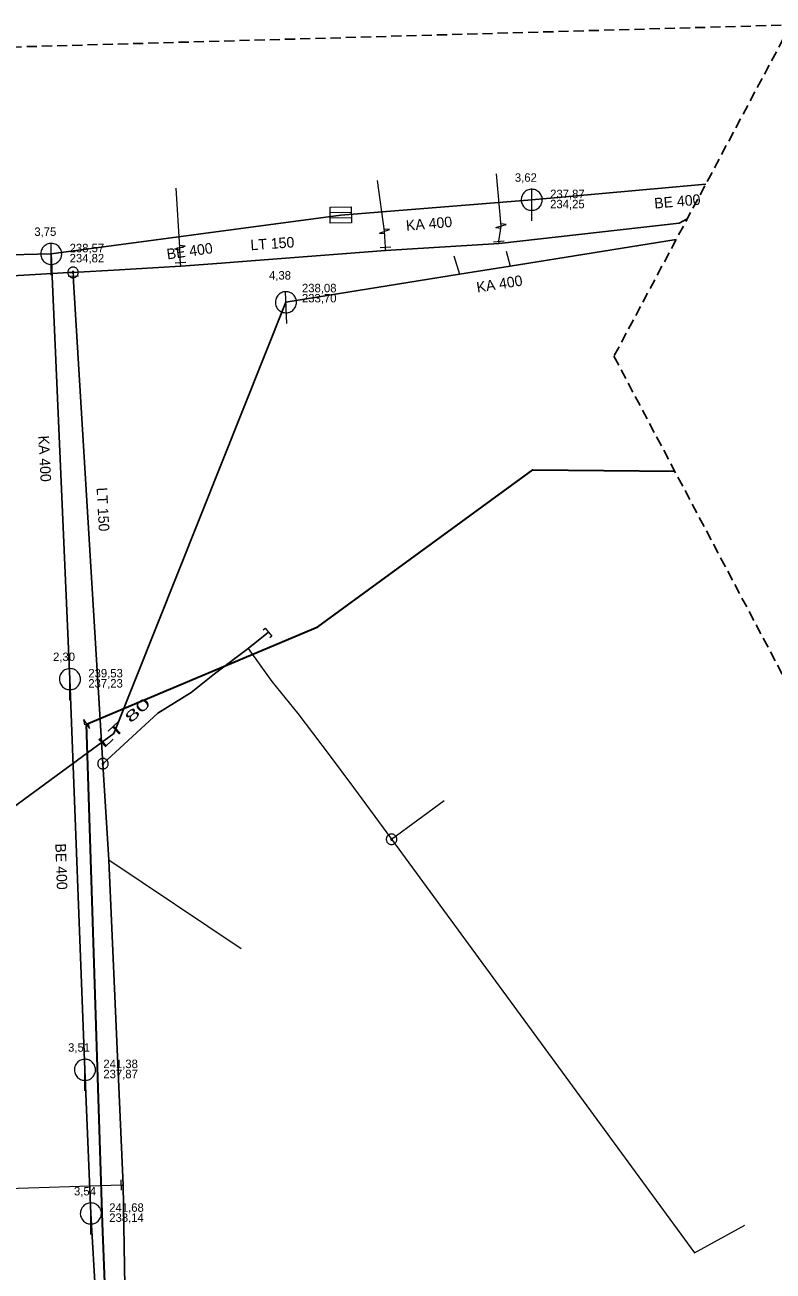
# Model space of a CAD drawing. Extents: x -777996 to -777727, y -976581 to -976199.
# Drawn here: x -777920.7 to -777849.8, y -976316.9 to -976198.8 of the extents above; entities that cross this region are included whole.
import ezdxf

# ---------------------------------------------------------------- set-up
doc = ezdxf.new("R2010")
doc.units = 0
doc.header["$LTSCALE"] = 0.32
doc.linetypes.add('MEDIUM_DASHED', pattern=[4.5, 3, -1.5])
for name, color, linetype, lineweight in [('1', 7, 'MEDIUM_DASHED', 25), ('11', 7, 'Continuous', 13), ('13', 7, 'Continuous', 13), ('14', 7, 'Continuous', 25), ('17', 7, 'Continuous', 25), ('22', 7, 'Continuous', 13), ('34', 7, 'Continuous', 13), ('47', 7, 'Continuous', 13)]:
    doc.layers.add(name, color=color, linetype=linetype, lineweight=lineweight)

msp = doc.modelspace()

# ---------------------------------------------------------------- linework, layer by layer
at = {"layer": '1'}
msp.add_lwpolyline([(-777995.417, -976203.033), (-777848.18, -976198.846), (-777864.927, -976230.247), (-777726.762, -976491.225), (-777789.565, -976581.242), (-777941.686, -976558.215), (-777989.136, -976405.396)], close=True, dxfattribs=at)
at = {"layer": '11'}
for p, q in [((-777880.085, -976220.714), (-777879.559, -976222.48)), ((-777875.137, -976220.301), (-777874.77, -976221.71))]:
    msp.add_line(p, q, dxfattribs=at)
at = {"layer": '13'}
for p, q in [((-777886.67, -976218.399), (-777887.346, -976213.598)), ((-777875.62, -976217.91), (-777876.065, -976212.971)), ((-777906.059, -976219.949), (-777906.417, -976214.321)), ((-777886.579, -976219.92), (-777886.67, -976218.399)), ((-777875.84, -976219.35), (-777875.62, -976217.91)), ((-777886.003, -976276.015), (-777881.024, -976272.355)), ((-777900.252, -976286.394), (-777912.789, -976277.989)), ((-777911.609, -976308.78), (-777933.447, -976309.493))]:
    msp.add_line(p, q, dxfattribs=at)
for points in [[(-777905.996, -976221.36), (-777906.014, -976221.018), (-777906.064, -976219.872)], [(-777899.57, -976257.94), (-777897.34, -976261.07), (-777894.89, -976264.09), (-777891.899, -976268), (-777889.601, -976271.12), (-777886.003, -976276.015)], [(-777886.003, -976276.015), (-777857.296, -976315.2), (-777852.537, -976312.587)]]:
    msp.add_lwpolyline(points, dxfattribs=at)
at = {"layer": '14'}
for p, q in [((-777872.715, -976215.421), (-777856.22, -976213.921)), ((-777890.804, -976216.868), (-777872.715, -976215.421)), ((-777918.245, -976220.55), (-777890.804, -976216.868)), ((-777935.509, -976220.899), (-777918.245, -976220.55)), ((-777916.475, -976260.84), (-777918.245, -976220.55)), ((-777915.05, -976297.862), (-777916.475, -976260.84)), ((-777914.489, -976311.478), (-777915.05, -976297.862)), ((-777912.781, -976340.699), (-777914.489, -976311.478))]:
    msp.add_line(p, q, dxfattribs=at)
at = {"layer": '14', "lineweight": 13}
for p, q in [((-777875.805, -976219.573), (-777875.84, -976219.35)), ((-777886.559, -976220.219), (-777886.579, -976219.92)), ((-777905.98, -976221.699), (-777905.996, -976221.36)), ((-777916.18, -976222.3), (-777916.155, -976222.666)), ((-777911.609, -976308.78), (-777911.427, -976308.781))]:
    msp.add_line(p, q, dxfattribs=at)
at = {"layer": '14'}
for points in [[(-777896.01, -976225.129), (-777879.559, -976222.48), (-777874.77, -976221.71), (-777859.024, -976219.178)], [(-777960.831, -976301.607), (-777912.32, -976266.008), (-777896.01, -976225.129)]]:
    msp.add_lwpolyline(points, dxfattribs=at)
at = {"layer": '17'}
msp.add_line((-777916.155, -976222.666), (-777913.344, -976268.857), dxfattribs=at)
for points in [[(-777916.18, -976222.3), (-777915.685, -976222.266), (-777912.3, -976222.1), (-777905.98, -976221.699), (-777902.108, -976221.408), (-777900.93, -976221.32), (-777886.559, -976220.219), (-777875.805, -976219.573), (-777858.75, -976217.62), (-777857.98, -976217.22)], [(-777929.246, -976223.038), (-777928.877, -976223.029), (-777916.57, -976222.32), (-777916.18, -976222.3)], [(-777913.344, -976268.857), (-777908.149, -976264.079), (-777904.989, -976262.12), (-777902.789, -976260.329), (-777899.57, -976257.94), (-777897.657, -976256.389)], [(-777913.344, -976268.857), (-777912.789, -976277.989), (-777911.427, -976308.781), (-777911.171, -976324.191), (-777910.419, -976354.125), (-777909.559, -976388.363), (-777908.825, -976391.646), (-777908.211, -976394.397)]]:
    msp.add_lwpolyline(points, dxfattribs=at)
at = {"layer": '17', "lineweight": 35}
for points in [[(-777914.899, -976265.1), (-777893, -976255.899), (-777872.6, -976241), (-777859.156, -976241.149)], [(-777904.212, -976563.887), (-777912, -976559.699), (-777928.6, -976551.899), (-777943.399, -976543.899), (-777945.899, -976539.199), (-777934, -976487.1), (-777919.8, -976463.1), (-777903.899, -976437), (-777908, -976421.399), (-777910, -976398.3), (-777913.399, -976312.399), (-777914.899, -976265.1)]]:
    msp.add_lwpolyline(points, dxfattribs=at)
at = {"layer": '22'}
for p, q in [((-777872.716, -976217.421), (-777872.715, -976214.421)), ((-777891.818, -976216.626), (-777889.818, -976216.597)), ((-777891.811, -976217.126), (-777889.811, -976217.096)), ((-777918.246, -976222.55), (-777918.245, -976219.55)), ((-777895.931, -976227.127), (-777896.049, -976224.13)), ((-777916.475, -976262.84), (-777916.474, -976259.84)), ((-777915.051, -976299.862), (-777915.05, -976296.862)), ((-777914.49, -976313.478), (-777914.489, -976310.478))]:
    msp.add_line(p, q, dxfattribs=at)
for points in [[(-777871.716, -976215.421), (-777871.721, -976215.312), (-777871.739, -976215.204), (-777871.769, -976215.098), (-777871.809, -976214.997), (-777871.861, -976214.9), (-777871.923, -976214.81), (-777871.995, -976214.727), (-777872.075, -976214.653), (-777872.163, -976214.587), (-777872.257, -976214.532), (-777872.357, -976214.487), (-777872.462, -976214.454), (-777872.569, -976214.432), (-777872.678, -976214.422), (-777872.788, -976214.424), (-777872.896, -976214.438), (-777873.003, -976214.463), (-777873.106, -976214.5), (-777873.204, -976214.549), (-777873.296, -976214.607), (-777873.382, -976214.676), (-777873.459, -976214.753), (-777873.528, -976214.839), (-777873.587, -976214.931), (-777873.635, -976215.029), (-777873.672, -976215.132), (-777873.698, -976215.239), (-777873.712, -976215.347), (-777873.715, -976215.457), (-777873.705, -976215.566), (-777873.684, -976215.673), (-777873.65, -976215.777), (-777873.606, -976215.877), (-777873.551, -976215.972), (-777873.485, -976216.06), (-777873.411, -976216.14), (-777873.328, -976216.212), (-777873.238, -976216.274), (-777873.142, -976216.326), (-777873.04, -976216.367), (-777872.935, -976216.397), (-777872.827, -976216.415), (-777872.717, -976216.421), (-777872.608, -976216.415), (-777872.5, -976216.397), (-777872.395, -976216.368), (-777872.293, -976216.327), (-777872.196, -976216.275), (-777872.106, -976216.213), (-777872.023, -976216.142), (-777871.948, -976216.062), (-777871.883, -976215.974), (-777871.827, -976215.88), (-777871.783, -976215.78), (-777871.749, -976215.676), (-777871.727, -976215.568), (-777871.717, -976215.459)], [(-777891.825, -976216.126), (-777889.826, -976216.097), (-777889.804, -976217.596), (-777891.803, -976217.626)], [(-777917.246, -976220.55), (-777917.251, -976220.441), (-777917.269, -976220.333), (-777917.299, -976220.227), (-777917.339, -976220.126), (-777917.391, -976220.029), (-777917.453, -976219.939), (-777917.525, -976219.856), (-777917.605, -976219.782), (-777917.693, -976219.716), (-777917.787, -976219.661), (-777917.887, -976219.616), (-777917.992, -976219.583), (-777918.099, -976219.561), (-777918.208, -976219.551), (-777918.318, -976219.553), (-777918.426, -976219.567), (-777918.533, -976219.592), (-777918.636, -976219.629), (-777918.734, -976219.678), (-777918.826, -976219.736), (-777918.912, -976219.805), (-777918.989, -976219.882), (-777919.058, -976219.968), (-777919.117, -976220.06), (-777919.165, -976220.158), (-777919.202, -976220.261), (-777919.228, -976220.368), (-777919.242, -976220.476), (-777919.245, -976220.586), (-777919.235, -976220.695), (-777919.214, -976220.802), (-777919.18, -976220.906), (-777919.136, -976221.006), (-777919.081, -976221.101), (-777919.015, -976221.189), (-777918.941, -976221.269), (-777918.858, -976221.341), (-777918.768, -976221.403), (-777918.672, -976221.455), (-777918.57, -976221.496), (-777918.465, -976221.526), (-777918.357, -976221.544), (-777918.247, -976221.55), (-777918.138, -976221.544), (-777918.03, -976221.526), (-777917.925, -976221.497), (-777917.823, -976221.456), (-777917.726, -976221.404), (-777917.636, -976221.342), (-777917.553, -976221.271), (-777917.478, -976221.191), (-777917.413, -976221.103), (-777917.357, -976221.009), (-777917.313, -976220.909), (-777917.279, -976220.805), (-777917.257, -976220.697), (-777917.247, -976220.588)], [(-777895.01, -976225.09), (-777895.021, -976224.981), (-777895.043, -976224.874), (-777895.077, -976224.769), (-777895.121, -976224.67), (-777895.177, -976224.575), (-777895.242, -976224.487), (-777895.317, -976224.407), (-777895.4, -976224.336), (-777895.491, -976224.274), (-777895.587, -976224.223), (-777895.689, -976224.182), (-777895.795, -976224.153), (-777895.903, -976224.135), (-777896.012, -976224.129), (-777896.122, -976224.136), (-777896.229, -976224.154), (-777896.335, -976224.183), (-777896.436, -976224.224), (-777896.532, -976224.277), (-777896.622, -976224.339), (-777896.705, -976224.411), (-777896.779, -976224.491), (-777896.845, -976224.58), (-777896.9, -976224.674), (-777896.944, -976224.774), (-777896.977, -976224.878), (-777896.999, -976224.986), (-777897.009, -976225.094), (-777897.006, -976225.204), (-777896.992, -976225.313), (-777896.967, -976225.419), (-777896.929, -976225.522), (-777896.881, -976225.62), (-777896.822, -976225.712), (-777896.753, -976225.798), (-777896.676, -976225.875), (-777896.59, -976225.944), (-777896.497, -976226.002), (-777896.399, -976226.05), (-777896.296, -976226.087), (-777896.19, -976226.113), (-777896.081, -976226.127), (-777895.971, -976226.128), (-777895.862, -976226.118), (-777895.755, -976226.096), (-777895.651, -976226.063), (-777895.551, -976226.018), (-777895.456, -976225.962), (-777895.369, -976225.896), (-777895.289, -976225.822), (-777895.217, -976225.739), (-777895.155, -976225.649), (-777895.103, -976225.553), (-777895.063, -976225.451), (-777895.033, -976225.346), (-777895.015, -976225.237), (-777895.01, -976225.128)], [(-777915.475, -976260.84), (-777915.48, -976260.731), (-777915.498, -976260.623), (-777915.528, -976260.517), (-777915.568, -976260.416), (-777915.62, -976260.319), (-777915.682, -976260.229), (-777915.754, -976260.146), (-777915.834, -976260.072), (-777915.922, -976260.006), (-777916.016, -976259.951), (-777916.116, -976259.906), (-777916.221, -976259.873), (-777916.328, -976259.851), (-777916.437, -976259.841), (-777916.547, -976259.843), (-777916.655, -976259.857), (-777916.762, -976259.882), (-777916.865, -976259.919), (-777916.963, -976259.968), (-777917.055, -976260.026), (-777917.141, -976260.095), (-777917.218, -976260.172), (-777917.287, -976260.258), (-777917.346, -976260.35), (-777917.394, -976260.448), (-777917.431, -976260.551), (-777917.457, -976260.658), (-777917.471, -976260.766), (-777917.474, -976260.876), (-777917.464, -976260.985), (-777917.443, -976261.092), (-777917.409, -976261.196), (-777917.365, -976261.296), (-777917.31, -976261.391), (-777917.244, -976261.479), (-777917.17, -976261.559), (-777917.087, -976261.631), (-777916.997, -976261.693), (-777916.901, -976261.745), (-777916.799, -976261.786), (-777916.694, -976261.816), (-777916.586, -976261.834), (-777916.476, -976261.84), (-777916.367, -976261.834), (-777916.259, -976261.816), (-777916.154, -976261.787), (-777916.052, -976261.746), (-777915.955, -976261.694), (-777915.865, -976261.632), (-777915.782, -976261.561), (-777915.707, -976261.481), (-777915.642, -976261.393), (-777915.586, -976261.299), (-777915.542, -976261.199), (-777915.508, -976261.095), (-777915.486, -976260.987), (-777915.476, -976260.878)], [(-777914.051, -976297.862), (-777914.056, -976297.753), (-777914.074, -976297.645), (-777914.104, -976297.539), (-777914.144, -976297.438), (-777914.196, -976297.341), (-777914.258, -976297.251), (-777914.33, -976297.168), (-777914.41, -976297.094), (-777914.498, -976297.028), (-777914.592, -976296.973), (-777914.692, -976296.928), (-777914.797, -976296.895), (-777914.904, -976296.873), (-777915.013, -976296.863), (-777915.123, -976296.865), (-777915.231, -976296.879), (-777915.338, -976296.904), (-777915.441, -976296.941), (-777915.539, -976296.99), (-777915.631, -976297.048), (-777915.717, -976297.117), (-777915.794, -976297.194), (-777915.863, -976297.28), (-777915.922, -976297.372), (-777915.97, -976297.47), (-777916.007, -976297.573), (-777916.033, -976297.68), (-777916.047, -976297.788), (-777916.05, -976297.898), (-777916.04, -976298.007), (-777916.019, -976298.114), (-777915.985, -976298.218), (-777915.941, -976298.318), (-777915.886, -976298.413), (-777915.82, -976298.501), (-777915.746, -976298.581), (-777915.663, -976298.653), (-777915.573, -976298.715), (-777915.477, -976298.767), (-777915.375, -976298.808), (-777915.27, -976298.838), (-777915.162, -976298.856), (-777915.052, -976298.862), (-777914.943, -976298.856), (-777914.835, -976298.838), (-777914.73, -976298.809), (-777914.628, -976298.768), (-777914.531, -976298.716), (-777914.441, -976298.654), (-777914.358, -976298.583), (-777914.283, -976298.503), (-777914.218, -976298.415), (-777914.162, -976298.321), (-777914.118, -976298.221), (-777914.084, -976298.117), (-777914.062, -976298.009), (-777914.052, -976297.9)], [(-777913.49, -976311.478), (-777913.495, -976311.369), (-777913.513, -976311.261), (-777913.543, -976311.155), (-777913.583, -976311.054), (-777913.635, -976310.957), (-777913.697, -976310.867), (-777913.769, -976310.784), (-777913.849, -976310.71), (-777913.937, -976310.644), (-777914.031, -976310.589), (-777914.131, -976310.544), (-777914.236, -976310.511), (-777914.343, -976310.489), (-777914.452, -976310.479), (-777914.562, -976310.481), (-777914.67, -976310.495), (-777914.777, -976310.52), (-777914.88, -976310.557), (-777914.978, -976310.606), (-777915.07, -976310.664), (-777915.156, -976310.733), (-777915.233, -976310.81), (-777915.302, -976310.896), (-777915.361, -976310.988), (-777915.409, -976311.086), (-777915.446, -976311.189), (-777915.472, -976311.296), (-777915.486, -976311.404), (-777915.489, -976311.514), (-777915.479, -976311.623), (-777915.458, -976311.73), (-777915.424, -976311.834), (-777915.38, -976311.934), (-777915.325, -976312.029), (-777915.259, -976312.117), (-777915.185, -976312.197), (-777915.102, -976312.269), (-777915.012, -976312.331), (-777914.916, -976312.383), (-777914.814, -976312.424), (-777914.709, -976312.454), (-777914.601, -976312.472), (-777914.491, -976312.478), (-777914.382, -976312.472), (-777914.274, -976312.454), (-777914.169, -976312.425), (-777914.067, -976312.384), (-777913.97, -976312.332), (-777913.88, -976312.27), (-777913.797, -976312.199), (-777913.722, -976312.119), (-777913.657, -976312.031), (-777913.601, -976311.937), (-777913.557, -976311.837), (-777913.523, -976311.733), (-777913.501, -976311.625), (-777913.491, -976311.516)]]:
    msp.add_lwpolyline(points, close=True, dxfattribs=at)
at = {"layer": '34'}
for p, q in [((-777876.337, -976219.397), (-777875.342, -976219.303)), ((-777887.077, -976219.953), (-777886.08, -976219.887)), ((-777906.495, -976221.384), (-777905.496, -976221.336)), ((-777915.655, -976222.645), (-777916.654, -976222.685)), ((-777911.592, -976309.279), (-777911.624, -976308.28))]:
    msp.add_line(p, q, dxfattribs=at)
at = {"layer": '47'}
for p, q in [((-777887.151, -976218.565), (-777886.641, -976218.598)), ((-777876.109, -976218.052), (-777875.601, -976218.11)), ((-777906.551, -976220.078), (-777906.046, -976220.149)), ((-777915.184, -976264.676), (-777915.085, -976265.177))]:
    msp.add_line(p, q, dxfattribs=at)
for points in [[(-777887.151, -976218.565), (-777886.188, -976218.232), (-777886.698, -976218.199)], [(-777876.109, -976218.052), (-777875.13, -976217.767), (-777875.638, -976217.709)], [(-777906.551, -976220.078), (-777905.566, -976219.819), (-777906.071, -976219.748)], [(-777898.173, -976256.181), (-777897.983, -976256.015), (-777897.33, -976256.762), (-777897.52, -976256.928)], [(-777915.184, -976264.676), (-777914.615, -976265.523), (-777914.714, -976265.022)]]:
    msp.add_lwpolyline(points, dxfattribs=at)
for points in [[(-777915.68, -976222.273), (-777915.686, -976222.221), (-777915.697, -976222.169), (-777915.713, -976222.12), (-777915.734, -976222.072), (-777915.761, -976222.027), (-777915.792, -976221.984), (-777915.827, -976221.946), (-777915.866, -976221.911), (-777915.908, -976221.88), (-777915.953, -976221.854), (-777916.001, -976221.832), (-777916.051, -976221.817), (-777916.102, -976221.806), (-777916.154, -976221.8), (-777916.206, -976221.8), (-777916.258, -976221.806), (-777916.31, -976221.817), (-777916.36, -976221.834), (-777916.407, -976221.854), (-777916.452, -976221.881), (-777916.495, -976221.912), (-777916.534, -976221.947), (-777916.569, -976221.986), (-777916.6, -976222.028), (-777916.625, -976222.073), (-777916.647, -976222.121), (-777916.663, -976222.171), (-777916.673, -976222.222), (-777916.679, -976222.274), (-777916.679, -976222.326), (-777916.673, -976222.378), (-777916.662, -976222.43), (-777916.646, -976222.48), (-777916.625, -976222.527), (-777916.598, -976222.572), (-777916.568, -976222.615), (-777916.533, -976222.654), (-777916.494, -976222.689), (-777916.451, -976222.72), (-777916.406, -976222.745), (-777916.358, -976222.767), (-777916.309, -976222.783), (-777916.257, -976222.793), (-777916.205, -976222.799), (-777916.153, -976222.799), (-777916.101, -976222.793), (-777916.049, -976222.782), (-777916, -976222.767), (-777915.952, -976222.745), (-777915.907, -976222.718), (-777915.864, -976222.688), (-777915.826, -976222.653), (-777915.791, -976222.614), (-777915.76, -976222.571), (-777915.734, -976222.526), (-777915.712, -976222.478), (-777915.697, -976222.429), (-777915.686, -976222.377), (-777915.68, -976222.325)], [(-777916.098, -976222.295), (-777916.098, -976222.286), (-777916.101, -976222.278), (-777916.103, -976222.27), (-777916.106, -976222.263), (-777916.111, -976222.255), (-777916.116, -976222.248), (-777916.122, -976222.241), (-777916.128, -976222.236), (-777916.135, -976222.231), (-777916.142, -976222.226), (-777916.151, -976222.223), (-777916.159, -976222.22), (-777916.167, -976222.219), (-777916.175, -976222.217), (-777916.184, -976222.218), (-777916.193, -976222.218), (-777916.201, -976222.221), (-777916.209, -976222.223), (-777916.216, -976222.226), (-777916.224, -976222.231), (-777916.231, -976222.236), (-777916.238, -976222.242), (-777916.243, -976222.248), (-777916.249, -976222.255), (-777916.253, -976222.262), (-777916.256, -976222.271), (-777916.259, -976222.279), (-777916.26, -976222.287), (-777916.262, -976222.295), (-777916.261, -976222.304), (-777916.261, -976222.313), (-777916.258, -976222.321), (-777916.256, -976222.329), (-777916.253, -976222.336), (-777916.248, -976222.344), (-777916.244, -976222.351), (-777916.237, -976222.358), (-777916.231, -976222.363), (-777916.224, -976222.369), (-777916.217, -976222.373), (-777916.208, -976222.376), (-777916.2, -976222.379), (-777916.192, -976222.38), (-777916.184, -976222.382), (-777916.175, -976222.381), (-777916.166, -976222.381), (-777916.158, -976222.378), (-777916.15, -976222.376), (-777916.143, -976222.373), (-777916.135, -976222.368), (-777916.128, -976222.364), (-777916.121, -976222.357), (-777916.116, -976222.351), (-777916.111, -976222.344), (-777916.106, -976222.337), (-777916.103, -976222.328), (-777916.1, -976222.32), (-777916.099, -976222.312), (-777916.097, -976222.304)], [(-777913.324, -976269.356), (-777913.272, -976269.351), (-777913.22, -976269.341), (-777913.171, -976269.325), (-777913.122, -976269.305), (-777913.076, -976269.279), (-777913.034, -976269.248), (-777912.995, -976269.214), (-777912.959, -976269.175), (-777912.928, -976269.134), (-777912.901, -976269.089), (-777912.879, -976269.041), (-777912.863, -976268.991), (-777912.851, -976268.941), (-777912.845, -976268.889), (-777912.844, -976268.837), (-777912.849, -976268.785), (-777912.859, -976268.733), (-777912.875, -976268.683), (-777912.895, -976268.635), (-777912.921, -976268.589), (-777912.952, -976268.547), (-777912.986, -976268.507), (-777913.025, -976268.471), (-777913.066, -976268.44), (-777913.111, -976268.414), (-777913.159, -976268.392), (-777913.209, -976268.375), (-777913.259, -976268.364), (-777913.311, -976268.358), (-777913.363, -976268.357), (-777913.415, -976268.362), (-777913.467, -976268.372), (-777913.517, -976268.387), (-777913.565, -976268.408), (-777913.611, -976268.434), (-777913.653, -976268.464), (-777913.693, -976268.498), (-777913.729, -976268.537), (-777913.76, -976268.579), (-777913.786, -976268.624), (-777913.808, -976268.672), (-777913.825, -976268.721), (-777913.836, -976268.772), (-777913.842, -976268.824), (-777913.843, -976268.876), (-777913.838, -976268.928), (-777913.828, -976268.98), (-777913.813, -976269.029), (-777913.792, -976269.078), (-777913.766, -976269.124), (-777913.736, -976269.166), (-777913.702, -976269.205), (-777913.663, -976269.241), (-777913.621, -976269.272), (-777913.576, -976269.299), (-777913.528, -976269.321), (-777913.479, -976269.337), (-777913.428, -976269.349), (-777913.376, -976269.355)], [(-777913.34, -976268.938), (-777913.331, -976268.938), (-777913.323, -976268.936), (-777913.315, -976268.933), (-777913.308, -976268.93), (-777913.3, -976268.926), (-777913.293, -976268.921), (-777913.286, -976268.915), (-777913.28, -976268.909), (-777913.276, -976268.902), (-777913.271, -976268.895), (-777913.267, -976268.886), (-777913.265, -976268.878), (-777913.263, -976268.87), (-777913.261, -976268.862), (-777913.262, -976268.853), (-777913.262, -976268.844), (-777913.264, -976268.836), (-777913.267, -976268.828), (-777913.27, -976268.821), (-777913.274, -976268.813), (-777913.279, -976268.806), (-777913.285, -976268.799), (-777913.291, -976268.793), (-777913.298, -976268.788), (-777913.305, -976268.784), (-777913.314, -976268.78), (-777913.322, -976268.778), (-777913.33, -976268.776), (-777913.338, -976268.774), (-777913.347, -976268.775), (-777913.356, -976268.775), (-777913.364, -976268.777), (-777913.372, -976268.78), (-777913.379, -976268.783), (-777913.387, -976268.787), (-777913.394, -976268.791), (-777913.401, -976268.798), (-777913.407, -976268.804), (-777913.412, -976268.811), (-777913.416, -976268.818), (-777913.42, -976268.827), (-777913.422, -976268.835), (-777913.424, -976268.843), (-777913.426, -976268.851), (-777913.425, -976268.86), (-777913.425, -976268.869), (-777913.423, -976268.877), (-777913.42, -976268.885), (-777913.417, -976268.892), (-777913.413, -976268.9), (-777913.409, -976268.907), (-777913.402, -976268.914), (-777913.396, -976268.92), (-777913.389, -976268.924), (-777913.382, -976268.929), (-777913.373, -976268.933), (-777913.365, -976268.935), (-777913.357, -976268.937), (-777913.349, -976268.939)], [(-777885.706, -976276.422), (-777885.666, -976276.389), (-777885.628, -976276.351), (-777885.596, -976276.311), (-777885.567, -976276.267), (-777885.543, -976276.22), (-777885.525, -976276.171), (-777885.512, -976276.121), (-777885.504, -976276.069), (-777885.501, -976276.017), (-777885.503, -976275.965), (-777885.512, -976275.912), (-777885.526, -976275.862), (-777885.544, -976275.814), (-777885.568, -976275.767), (-777885.596, -976275.723), (-777885.629, -976275.683), (-777885.667, -976275.645), (-777885.708, -976275.613), (-777885.751, -976275.584), (-777885.798, -976275.56), (-777885.847, -976275.542), (-777885.898, -976275.528), (-777885.95, -976275.52), (-777886.001, -976275.517), (-777886.053, -976275.52), (-777886.106, -976275.529), (-777886.156, -976275.542), (-777886.204, -976275.561), (-777886.251, -976275.585), (-777886.295, -976275.613), (-777886.335, -976275.646), (-777886.373, -976275.684), (-777886.406, -976275.724), (-777886.434, -976275.768), (-777886.458, -976275.815), (-777886.477, -976275.863), (-777886.49, -976275.914), (-777886.498, -976275.966), (-777886.501, -976276.018), (-777886.498, -976276.07), (-777886.489, -976276.123), (-777886.476, -976276.173), (-777886.457, -976276.221), (-777886.433, -976276.268), (-777886.405, -976276.312), (-777886.372, -976276.352), (-777886.334, -976276.39), (-777886.295, -976276.422), (-777886.25, -976276.451), (-777886.203, -976276.475), (-777886.155, -976276.494), (-777886.104, -976276.507), (-777886.053, -976276.515), (-777886, -976276.517), (-777885.948, -976276.515), (-777885.895, -976276.506), (-777885.846, -976276.493), (-777885.797, -976276.474), (-777885.75, -976276.45)], [(-777885.952, -976276.084), (-777885.945, -976276.078), (-777885.94, -976276.072), (-777885.934, -976276.066), (-777885.93, -976276.059), (-777885.926, -976276.051), (-777885.923, -976276.043), (-777885.92, -976276.034), (-777885.919, -976276.026), (-777885.919, -976276.017), (-777885.919, -976276.009), (-777885.92, -976276), (-777885.923, -976275.992), (-777885.926, -976275.984), (-777885.929, -976275.976), (-777885.934, -976275.969), (-777885.94, -976275.962), (-777885.946, -976275.957), (-777885.952, -976275.951), (-777885.959, -976275.947), (-777885.967, -976275.943), (-777885.975, -976275.94), (-777885.984, -976275.937), (-777885.992, -976275.936), (-777886.001, -976275.935), (-777886.009, -976275.936), (-777886.018, -976275.937), (-777886.026, -976275.94), (-777886.034, -976275.943), (-777886.042, -976275.946), (-777886.049, -976275.951), (-777886.056, -976275.957), (-777886.061, -976275.963), (-777886.067, -976275.969), (-777886.071, -976275.976), (-777886.075, -976275.984), (-777886.079, -976275.992), (-777886.081, -976276.001), (-777886.082, -976276.009), (-777886.083, -976276.018), (-777886.082, -976276.026), (-777886.081, -976276.035), (-777886.078, -976276.043), (-777886.075, -976276.051), (-777886.072, -976276.059), (-777886.067, -976276.066), (-777886.061, -976276.073), (-777886.055, -976276.078), (-777886.049, -976276.084), (-777886.042, -976276.088), (-777886.034, -976276.092), (-777886.026, -976276.096), (-777886.017, -976276.098), (-777886.009, -976276.099), (-777886, -976276.099), (-777885.992, -976276.099), (-777885.983, -976276.098), (-777885.975, -976276.095), (-777885.967, -976276.092), (-777885.959, -976276.089)]]:
    msp.add_lwpolyline(points, close=True, dxfattribs=at)

# ---------------------------------------------------------------- texts
at = {"layer": '1'}
for s, p in [('3,62', (-777874.316, -976213.709)), ('3,75', (-777919.845, -976218.838)), ('4,38', (-777897.61, -976222.977)), ('2,30', (-777918.074, -976259.128)), ('3,51', (-777916.65, -976296.15)), ('3,54', (-777916.09, -976309.766))]:
    msp.add_text(s, height=0.8, dxfattribs=at).set_placement(p)
for s, rotation, p in [('BE 400', 5, (-777861.062, -976216.256)), ('KA 400', 5, (-777884.591, -976218.362)), ('BE 400', 8, (-777907.233, -976221.075)), ('LT 150', 4, (-777899.335, -976220.205)), ('KA 400', 9, (-777877.866, -976224.221)), ('KA 400', 273, (-777919.475, -976237.784)), ('LT 150', 273, (-777913.948, -976242.706)), ('BE 400', 272, (-777917.861, -976276.429))]:
    msp.add_text(s, height=1, rotation=rotation, dxfattribs=at).set_placement(p)
at = {"layer": '1', "width": 1.8}
msp.add_text('LT 80 ', height=1, rotation=43, dxfattribs=at).set_placement((-777913.253, -976267.435))
at = {"layer": '22'}
for s, p in [('237,87', (-777870.973, -976215.261)), ('234,25', (-777870.973, -976216.221)), ('238,57', (-777916.503, -976220.389)), ('234,82', (-777916.503, -976221.349)), ('238,08', (-777894.488, -976224.181)), ('233,70', (-777894.488, -976225.141)), ('239,53', (-777914.732, -976260.679)), ('237,23', (-777914.732, -976261.639)), ('241,38', (-777913.308, -976297.701)), ('237,87', (-777913.308, -976298.661)), ('241,68', (-777912.747, -976311.318)), ('238,14', (-777912.747, -976312.278))]:
    msp.add_text(s, height=0.8, dxfattribs=at).set_placement(p)

doc.saveas('drawing.dxf')
